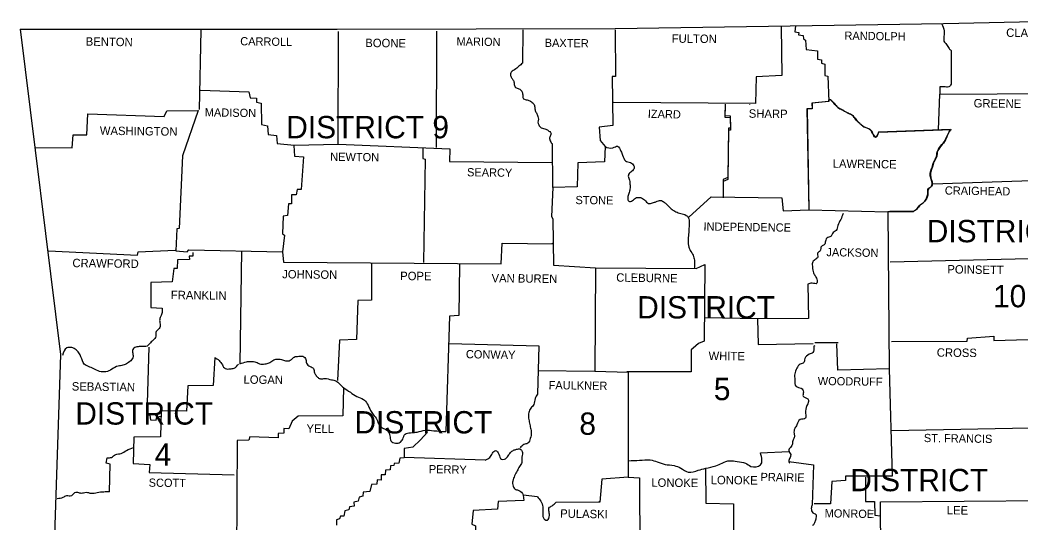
# Model space of a CAD drawing. Extents: x -42408 to 34530, y -43140 to 20491.
# Drawn here: x 1618 to 4174, y -21499 to -20216 of the extents above; entities that cross this region are included whole.
import ezdxf

# ---------------------------------------------------------------- set-up
doc = ezdxf.new("R2010")
doc.units = 0
for name, color, linetype in [('1', 7, 'Continuous'), ('2', 7, 'Continuous'), ('3', 7, 'Continuous'), ('S_MISC_BOUNDARY', 7, 'Continuous')]:
    doc.layers.add(name, color=color, linetype=linetype)

msp = doc.modelspace()

# ---------------------------------------------------------------- linework, layer by layer
at = {"layer": '1'}
for p, q in [((3966.6, -20386.8), (3966.6, -20405.3)), ((3688.2, -20420.3), (3682.6, -20420.5)), ((3994.6, -20496), (3810.4, -20502.4)), ((3963.1, -20497.5), (3964, -20496.6)), ((3802.9, -20516), (3807.7, -20511.2)), ((3647.7, -21040.7), (3707.3, -21040.7))]:
    msp.add_line(p, q, dxfattribs=at)
for points in [[(1618, -20239.1), (2427.6, -20239.6), (3138, -20238.1), (3976.1, -20225.1), (4364.6, -20216.1)], [(1618, -20239.1), (1721.6, -21071.2), (1676.6, -22429.5)], [(2080.1, -20242.1), (2075.6, -20444.9)], [(2079.1, -20395.3), (2202.3, -20399.3), (2205.3, -20415.3), (2222.3, -20415.8), (2221.8, -20425.8), (2233.8, -20428.8), (2234.8, -20483.4), (2250.3, -20486.9), (2251.3, -20508.5), (2273.3, -20511.5), (2274.3, -20531.5), (2317.9, -20536), (2430.1, -20533.5), (2431.1, -20245.6)], [(2681.9, -20244.6), (2680.4, -20542)], [(2902.2, -20241.1), (2901.2, -20326.7)], [(3138, -20241.1), (3139, -20360.3), (3130.5, -20360.8), (3132, -20485.4), (3096.9, -20490.4), (3099.9, -20524), (3112, -20539.5), (3111, -20579), (3042.9, -20581.6), (3040.4, -20642.6), (2978.3, -20644.6), (2975.3, -20718.7), (2978.8, -20724.7), (2980.3, -20842.9), (3087.4, -20849.9), (3085.9, -21113.8), (3171, -21116.3), (3171, -21384.6), (3104, -21389.6), (3098.9, -21448.7), (2986.3, -21449.2)], [(3562.1, -20233.6), (3563.1, -20357.8), (3498, -20361.3), (3496, -20429.3), (3134, -20427.3)], [(3598.5, -20230.9), (3596.6, -20246.1), (3606.6, -20247.6), (3606.1, -20253.6), (3617.6, -20256.1), (3618.6, -20264.1), (3624.1, -20267.6), (3625.7, -20291.7), (3654.2, -20294.7), (3654.2, -20316.2), (3664.7, -20317.7), (3664.7, -20326.2), (3673.7, -20328.7), (3673.2, -20357.8), (3681.2, -20359.3), (3683.2, -20424.8), (3640.7, -20428.8), (3641.2, -20442.9), (3628.2, -20443.4), (3632.7, -20701.7), (3834.4, -20706.2), (3837.9, -21107.8), (3706.3, -21111.3), (3703.8, -21043.7)], [(3995.6, -20293.7), (3996.1, -20380.3)], [(3682.6, -20420.5), (3682.7, -20424.8), (3640.2, -20428.8), (3640.7, -20442.9), (3627.7, -20443.4), (3632.2, -20701.7), (3833.9, -20706.2)], [(3964, -20497.1), (3966.6, -20405.3), (3966.6, -20405.3), (4259.5, -20403.8), (4263.5, -20442.9), (4346.1, -20439.9)], [(1657.5, -20542), (1751.2, -20542.5), (1753.7, -20509.5), (1788.2, -20509.5), (1791.2, -20455.9), (1986.5, -20462.9), (1992.5, -20447.9), (2073.1, -20447.4), (2032.5, -20563.5), (2024.5, -20749.3), (2018.5, -20749.8), (2015.5, -20805.9), (2045, -20808.4), (2049.5, -20803.8), (2288.4, -20808.4), (2290.9, -20834.9)], [(3418.9, -20430.9), (3417.9, -20459.9), (3431.9, -20460.9), (3432.4, -20492.9), (3427.4, -20492.9), (3425.4, -20619.1), (3413.9, -20624.1), (3413.9, -20666.2)], [(3418.9, -20435.4), (3417.9, -20464.4), (3431.9, -20465.4), (3432.4, -20497.4), (3427.4, -20497.4), (3425.4, -20623.6), (3413.9, -20628.6), (3413.9, -20670.7)], [(3481.5, -20431.9), (3482, -20431.4)], [(3810.9, -20502.4), (3996.6, -20495.9)], [(3994.6, -20496.4), (3994.6, -20496)], [(2316.9, -20537), (2318.9, -20564), (2341.9, -20565.5), (2335.9, -20649.6), (2325.4, -20649.1), (2323.4, -20662.7), (2311.4, -20662.7), (2310.9, -20685.7), (2303.4, -20686.2), (2300.9, -20715.7), (2289.9, -20717.2), (2288.4, -20762.3), (2293.4, -20765.8), (2288.4, -20808.4)], [(2430.1, -20533.5), (2715.4, -20545.5), (2714.9, -20578), (2976.8, -20580.1)], [(2646.8, -20544), (2646.3, -20570), (2652.9, -20571.5), (2648.8, -20835.9)], [(2978.3, -20644.6), (2977.8, -20532)], [(3949.1, -20634.6), (4227, -20625.6), (4243.5, -20606.6)], [(3325.8, -20719.7), (3382.8, -20668.2), (3563.1, -20670.7), (3566.6, -20704.2), (3632.2, -20701.7)], [(3833.9, -20706.2), (3838.4, -20705.2), (3899.5, -20705.2)], [(3900, -20705.2), (3838.9, -20705.2), (3834.4, -20706.2)], [(1690.6, -20806.4), (1918.4, -20816.9), (1919.4, -20808.9), (2014.5, -20804.3)], [(2183.2, -20806.4), (2179.7, -21095.2)], [(2290.9, -20834.9), (2846.6, -20839.4), (2849.1, -20786.8), (2978.3, -20788.3)], [(2976.8, -20787.8), (2978.3, -20786.3)], [(2059.6, -20810.4), (2059.6, -20819.4), (2050, -20819.4), (2050.5, -20828.4), (2020, -20828.9), (2019.5, -20851.4), (2011, -20851.4), (2006.5, -20885), (1952.4, -20887.5), (1951.9, -20951), (1981, -20953)], [(4301.1, -20824.4), (3839.9, -20834.9)], [(2515.7, -20838.9), (2515.2, -20932.5), (2480.6, -20933), (2477.6, -21032.7), (2433.6, -21034.2), (2428.6, -21137.3)], [(2740, -20841.4), (2739, -20971.6), (2714.9, -20973.6), (2705.4, -21268)], [(3087.4, -20849.9), (3344.8, -20851.4), (3366.8, -20840.9), (3365.3, -21036.7), (3350.3, -21043.2), (3336.8, -21054.7), (3332.3, -21059.2), (3331.8, -21115.3), (3168, -21115.3)], [(3630.2, -20891), (3631.2, -20979.1), (3501, -20979.6), (3367.3, -20977.1)], [(3501, -20979.6), (3503, -21045.2), (3643.7, -21042.7)], [(3843.9, -21037.7), (4037.2, -21036.7), (4037.7, -21029.7), (4104.8, -21024.6), (4104.8, -21035.2), (4396.2, -21027.1)], [(1946.9, -21052.2), (1941.9, -21224.4), (1949.4, -21226.4), (1950.9, -21238.4), (1965.9, -21239.4), (1967.4, -21230.9), (1979.5, -21228.9)], [(2713.9, -21043.2), (2942.7, -21048.7), (2939.7, -21172.3)], [(3647.7, -21049.2), (3645.2, -21049.7)], [(2115.1, -21079.2), (2111.6, -21150.8), (2046.5, -21151.3), (2043, -21216.4), (1978.5, -21214.9), (1976.5, -21282), (1908.9, -21282.5), (1906.9, -21349.6), (1949.4, -21352.1), (1947.9, -21372.6), (2165.2, -21378.6)], [(2940.2, -21111.8), (3085.9, -21113.8)], [(3837.9, -21107.8), (3845.4, -21382.1), (3726.3, -21382.6), (3725.8, -21393.6), (3691.2, -21395.6), (3688.2, -21452.7), (3646.2, -21452.7)], [(2444.1, -21155.8), (2442.1, -21227.9), (2327.9, -21228.4), (2312.9, -21241.4), (2304.4, -21261.5), (2291.9, -21260.5), (2291.4, -21272), (2276.9, -21273.5), (2277.4, -21284), (2204.8, -21282), (2202.3, -21290), (2172.2, -21291), (2171.2, -21583.9)], [(3843.9, -21265.5), (4241.5, -21257.5)], [(2658.9, -21270), (2640.8, -21289.5), (2621.3, -21308), (2598.8, -21311.5), (2598.8, -21335.1), (2587.8, -21336.6), (2585.8, -21348.6), (2573.2, -21349.6), (2572.2, -21355.1), (2563.7, -21355.6), (2563.2, -21366.1), (2551.2, -21366.6), (2550.2, -21378.6), (2540.2, -21378.6), (2540.7, -21392.6), (2529.7, -21391.6), (2529.2, -21402.6), (2515.7, -21403.6), (2511.7, -21421.7), (2494.6, -21423.2), (2493.1, -21433.2), (2484.1, -21435.7), (2481.6, -21446.2), (2470.1, -21448.7), (2471.1, -21459.2), (2459.6, -21460.2), (2457.6, -21468.2), (2447.1, -21471.2), (2444.6, -21484.8), (2436.6, -21484.3), (2434.1, -21491.3), (2426.6, -21493.8), (2426.1, -21507.3)], [(3509, -21322.5), (3581.6, -21319)], [(1846.3, -21422.2), (1847.8, -21351.6), (1837.8, -21348.6), (1840.8, -21335.1)], [(2805.6, -21341.1), (2599.3, -21334.6)], [(3368.8, -21361.6), (3369.8, -21451.2), (3440.4, -21452.7), (3440.9, -21645)], [(3581.6, -21345.1), (3644.2, -21353.1), (3640.7, -21455.2)], [(3171, -21384.6), (3200.1, -21386.6), (3200.6, -21577.9), (3174.5, -21686.5), (3230.1, -21689), (3229.6, -21781.2)], [(3777.4, -21385.1), (3776.9, -21447.2), (3799.9, -21447.2), (3800.9, -21481.8), (3815.4, -21483.3)], [(2939.2, -21434.7), (2903.2, -21430.7), (2904.7, -21444.2), (2839.1, -21446.7), (2837.1, -21466.2), (2775.5, -21469.7), (2772, -21504.8), (2781, -21509.3), (2781, -21532.3)], [(3096.4, -21448.2), (3098.9, -21445.7)], [(3843.9, -21891.3), (3883, -21888.8), (3882.5, -21787.2), (3845.9, -21784.7), (3847.9, -21585.9), (3816.4, -21581.4), (3815.4, -21447.7), (4242.5, -21444.7)]]:
    msp.add_lwpolyline(points, dxfattribs=at)
for points in [[(3971.3, -20225.1), (3978.1, -20244.1), (3977.6, -20257.6), (3977.6, -20270.1), (3984.1, -20278.6), (3990.6, -20289.2), (3995.6, -20293.7)], [(2901.2, -20326.7), (2892.2, -20334.2), (2884.2, -20341.2), (2872.1, -20349.7), (2870.6, -20357.8), (2874.6, -20365.8), (2878.7, -20372.3), (2880.2, -20381.3), (2883.7, -20388.8), (2892.2, -20391.8), (2899.2, -20398.3), (2901.7, -20407.3), (2902.7, -20415.8), (2910.7, -20419.8), (2919.7, -20422.8), (2928.2, -20428.8), (2932.2, -20436.4), (2933.2, -20445.9), (2936.7, -20453.4), (2940.7, -20462.4), (2941.7, -20469.9), (2940.7, -20477.4), (2942.7, -20484.4), (2949.2, -20491.4), (2960.8, -20494.9), (2968.8, -20499.9), (2974.3, -20507), (2970.8, -20515.5), (2971.3, -20523), (2975.8, -20532)], [(3996.1, -20380.3), (3989.6, -20386.8), (3977.1, -20386.8), (3966.6, -20386.8)], [(3810.4, -20502.4), (3802.4, -20516), (3794.9, -20505.5), (3789.4, -20496.9), (3772.8, -20488.9), (3762.3, -20480.4), (3751.8, -20469.9), (3744.3, -20460.4), (3732.8, -20454.4), (3719.8, -20446.9), (3708.8, -20441.4), (3699.2, -20431.9), (3688.2, -20420.3)], [(3688.7, -20420.3), (3699.8, -20431.9), (3709.3, -20441.4), (3720.3, -20446.9), (3733.3, -20454.4), (3744.8, -20460.4), (3752.3, -20469.9), (3762.8, -20480.4), (3773.3, -20488.9), (3789.9, -20496.9), (3795.4, -20505.5), (3802.9, -20516), (3810.9, -20502.4)], [(3899.5, -20705.2), (3907, -20700.2), (3917, -20688.7), (3926.6, -20681.2), (3933.1, -20671.2), (3936.1, -20661.2), (3938.1, -20646.6), (3945.6, -20641.1), (3946.6, -20629.6), (3943.1, -20617.1), (3943.1, -20604.6), (3947.6, -20592.6), (3951.6, -20578.5), (3958.6, -20564.5), (3960.1, -20554), (3969.1, -20538.5), (3981.1, -20522.5), (3987.1, -20508.5), (3994.6, -20496.4)], [(3995.1, -20496.4), (3987.6, -20508.5), (3981.6, -20522.5), (3969.6, -20538.5), (3960.6, -20554), (3959.1, -20564.5), (3952.1, -20578.5), (3948.1, -20592.6), (3943.6, -20604.6), (3943.6, -20617.1), (3947.1, -20629.6), (3946.1, -20641.1), (3938.6, -20646.6), (3936.6, -20661.2), (3933.6, -20671.2), (3927.1, -20681.2), (3917.5, -20688.7), (3907.5, -20700.2), (3900, -20705.2)], [(3112, -20539.5), (3132, -20543), (3144, -20538.5), (3152.5, -20551.5), (3157, -20561.5), (3164.5, -20576), (3176.6, -20580.6), (3185.6, -20588.6), (3185.6, -20597.1), (3177.6, -20605.1), (3171.5, -20613.1), (3173.5, -20622.6), (3175.6, -20635.6), (3175.6, -20648.1), (3172.5, -20659.7), (3170, -20670.2), (3172.5, -20679.2), (3182.1, -20677.7), (3192.1, -20670.2), (3202.6, -20670.2), (3212.6, -20675.7), (3223.1, -20685.2), (3233.6, -20683.2), (3242.1, -20680.7), (3254.2, -20677.2), (3262.7, -20681.7), (3270.2, -20687.7), (3279.2, -20697.2), (3287.7, -20703.2), (3298.7, -20708.7), (3312.2, -20712.2), (3324.7, -20720.7), (3326.8, -20735.3), (3326.3, -20747.8), (3325.3, -20763.3), (3324.2, -20780.3), (3325.8, -20796.8), (3331.3, -20807.9), (3338.3, -20820.9), (3340.3, -20832.9), (3339.8, -20851.9)], [(3719.8, -20710.7), (3713.8, -20726.2), (3706.8, -20741.3), (3702.3, -20754.3), (3692.7, -20761.8), (3689.7, -20768.8), (3681.2, -20771.8), (3674.7, -20781.8), (3671.7, -20790.8), (3664.7, -20794.8), (3661.2, -20805.9), (3654.7, -20811.9), (3655.2, -20821.9), (3647.7, -20828.9), (3641.7, -20836.9), (3641.7, -20847.9), (3644.2, -20862.4), (3649.2, -20870.9), (3653.7, -20882), (3653.2, -20889), (3640.7, -20889), (3630.2, -20891)], [(1981, -20953), (1981, -20963.6), (1977, -20974.6), (1974.4, -20984.1), (1976, -20996.6), (1971.4, -21006.6), (1964.9, -21014.6), (1964.9, -21024.6), (1957.4, -21035.2), (1949.4, -21043.2), (1942.4, -21049.7), (1929.9, -21050.7), (1919.4, -21051.2), (1908.9, -21054.7), (1904.9, -21062.2), (1906.9, -21073.7), (1902.9, -21084.7), (1892.3, -21093.2), (1880.8, -21098.7), (1868.8, -21100.7), (1852.3, -21108.8), (1837.3, -21115.3), (1821.2, -21114.3), (1806.2, -21107.8), (1792.7, -21101.7), (1782.2, -21095.7), (1773.7, -21077.2), (1768.2, -21067.2), (1758.7, -21057.2), (1747.1, -21053.2), (1737.6, -21054.2), (1726.1, -21073.7)], [(3645.2, -21049.7), (3642.7, -21066.2), (3633.2, -21070.7), (3622.1, -21081.7), (3619.6, -21091.7), (3610.6, -21095.7), (3602.1, -21106.3), (3596.6, -21120.8), (3596.6, -21135.8), (3600.1, -21152.8), (3612.6, -21157.3), (3618.6, -21167.3), (3617.6, -21177.8), (3629.7, -21184.9), (3631.7, -21190.9), (3629.7, -21197.4), (3624.1, -21215.9), (3624.6, -21228.4), (3623.6, -21233.9), (3610.1, -21237.4), (3602.1, -21250.9), (3596.6, -21260.5), (3594.6, -21273), (3596.1, -21282), (3592.1, -21289), (3590.6, -21299.5), (3585.6, -21308.5), (3581.1, -21317), (3586.1, -21327), (3584.6, -21334.1), (3581.6, -21345.1), (3584.1, -21348.6)], [(2115.1, -21079.2), (2126.2, -21086.2), (2134.7, -21097.7), (2142.2, -21107.3), (2154.7, -21107.8), (2164.7, -21105.8), (2176.2, -21095.7)], [(2179.7, -21095.2), (2196.2, -21089.7), (2208.3, -21088.7), (2220.3, -21090.7), (2232.8, -21095.7), (2246.3, -21094.7), (2256.3, -21091.2), (2266.3, -21084.7), (2277.4, -21082.7), (2287.9, -21084.7), (2298.9, -21087.7), (2310.9, -21084.2), (2317.9, -21077.7), (2329.9, -21075.7), (2340.4, -21075.7), (2347.9, -21084.2), (2349.4, -21093.2), (2359, -21101.7), (2367.5, -21107.3), (2370, -21117.8), (2374.5, -21125.3), (2379, -21130.3), (2385.5, -21133.3), (2396.5, -21132.3), (2413.5, -21135.8), (2424.5, -21138.3), (2434.6, -21146.8), (2444.1, -21155.8)], [(2444.1, -21155.8), (2461.6, -21167.8), (2478.1, -21178.3), (2495.1, -21185.9), (2504.7, -21196.9), (2513.2, -21213.9), (2520.2, -21224.4), (2529.2, -21237.4), (2535.7, -21251.9), (2546.2, -21260), (2557.2, -21267), (2562.7, -21279.5), (2565.2, -21292), (2577.3, -21298), (2588.8, -21295.5), (2595.3, -21288), (2601.3, -21275), (2614.8, -21271), (2632.3, -21269.5), (2652.4, -21265), (2674.4, -21266), (2705.4, -21268)], [(2939.7, -21172.3), (2933.2, -21183.9), (2930.2, -21198.9), (2922.2, -21208.4), (2917.2, -21219.4), (2916.7, -21233.9), (2919.2, -21246.9), (2921.7, -21259.5), (2923.7, -21271), (2921.2, -21285.5), (2914.7, -21298), (2904.7, -21301.5), (2895.2, -21310)], [(1840.8, -21335.1), (1851.8, -21334.1), (1862.3, -21327), (1876.3, -21324), (1890.3, -21316.5), (1907.9, -21308.5)], [(2805.6, -21341.1), (2818.1, -21334.1), (2824.6, -21323.5), (2832.6, -21317), (2840.6, -21326), (2847.6, -21339.1), (2855.1, -21339.1), (2864.6, -21330.1), (2870.6, -21322), (2878.2, -21316), (2886.2, -21313.5), (2894.7, -21312.5), (2901.2, -21322), (2899.2, -21337.1), (2899.2, -21347.1), (2893.7, -21357.6), (2887.7, -21368.6), (2881.2, -21381.1), (2876.2, -21394.6), (2877.2, -21407.7), (2884.2, -21416.2), (2892.2, -21418.7), (2903.2, -21429.7)], [(3172, -21342.6), (3200.1, -21341.6), (3227.6, -21340.6), (3245.1, -21345.6), (3265.2, -21352.1), (3288.7, -21355.1), (3305.2, -21361.6), (3324.7, -21371.6), (3349.8, -21367.1), (3369.3, -21362.1), (3394.8, -21355.6), (3411.4, -21348.6), (3430.4, -21342.6), (3449.4, -21345.1), (3470.9, -21349.1), (3484.5, -21357.1), (3509, -21353.6), (3509, -21322.5)], [(1846.3, -21422.2), (1831.8, -21422.7), (1815.2, -21424.7), (1800.2, -21426.7), (1786.7, -21424.2), (1774.2, -21426.2), (1765.7, -21424.2), (1755.2, -21426.7), (1749.1, -21432.7), (1736.6, -21432.7), (1727.6, -21436.7), (1713.1, -21440.2)], [(2939.2, -21434.7), (2947.7, -21445.7), (2952.8, -21460.7), (2952.8, -21477.7), (2956.8, -21491.8), (2964.8, -21494.8), (2969.8, -21482.8), (2968.8, -21470.7), (2968.8, -21463.7), (2977.3, -21457.7), (2986.3, -21449.2)], [(3640.7, -21455.2), (3638.7, -21465.2), (3642.7, -21475.7), (3649.7, -21479.3), (3650.7, -21489.3), (3648.2, -21499.3), (3646.2, -21503.3), (3641.7, -21509.3)]]:
    msp.add_spline(points, degree=3, dxfattribs=at)
at = {"layer": 'S_MISC_BOUNDARY'}
msp.add_line((3688.7, -20420.3), (3683.1, -20420.5), dxfattribs=at)

# ---------------------------------------------------------------- texts
at = {"layer": '2'}
for s, height, rotation, p in [('CLAY', 21.52, 359.2258, (4136.3, -20259.1)), ('BENTON', 21.53, 359.2527, (1785.7, -20281.7)), ('CARROLL', 21.03, 359.1481, (2180.2, -20280.7)), ('BOONE', 21.53, 359.4001, (2499.6, -20285.2)), ('MARION', 21.03, 359.1854, (2732.5, -20281.2)), ('BAXTER', 21.03, 359.2559, (2957.8, -20284.7)), ('FULTON', 21.52, 359.4996, (3282.2, -20274.1)), ('RANDOLPH', 21.03, 359.2583, (3723.3, -20266.6)), ('GREENE', 21.53, 359.2361, (4053.2, -20439.4)), ('MADISON', 21.03, 359.0906, (2089.6, -20462.4)), ('IZARD', 21.02, 358.9258, (3221.1, -20466.4)), ('SHARP', 21.52, 359.3905, (3479, -20465.9)), ('WASHINGTON', 21.52, 359.232, (1821.7, -20509.5)), ('NEWTON', 21.03, 359.2717, (2410, -20576)), ('LAWRENCE', 21.53, 359.2678, (3693.3, -20593.7)), ('SEARCY', 21.02, 359.2527, (2759.5, -20615.6)), ('CRAIGHEAD', 21.03, 359.1159, (3979.6, -20662.2)), ('STONE', 21.02, 359.4001, (3036.4, -20686.7)), ('INDEPENDENCE', 21.022, 359.2187, (3363.3, -20754.3)), ('JACKSON', 21.02, 359.1352, (3677.2, -20819.9)), ('CRAWFORD', 21.52, 359.2771, (1751.7, -20847.9)), ('JOHNSON', 21.53, 359.3514, (2287.4, -20876.4)), ('POINSETT', 21.52, 359.1987, (3986.1, -20863.9)), ('POPE', 21.53, 359.6155, (2588.8, -20881)), ('VAN BUREN', 21.53, 359.3508, (2822.1, -20886.5)), ('CLEBURNE', 21.52, 359.2535, (3140.5, -20885)), ('FRANKLIN', 21.53, 359.1815, (2003, -20929.5)), ('CONWAY', 21.02, 359.0371, (2756.5, -21080.7)), ('CROSS', 21.52, 359.3839, (3959.1, -21076.7)), ('WHITE', 21.53, 359.3139, (3376.3, -21085.2)), ('LOGAN', 21.53, 359.3969, (2188.7, -21145.8)), ('FAULKNER', 21.03, 359.2486, (2967.8, -21159.8)), ('WOODRUFF', 21.02, 359.2748, (3655.2, -21149.3)), ('SEBASTIAN', 21.52, 359.2816, (1750.1, -21163.3)), ('YELL', 21.53, 359.1987, (2349.4, -21271)), ('ST. FRANCIS', 21.022, 359.2216, (3926.1, -21295)), ('PERRY', 21.03, 359.0858, (2661.9, -21374.6)), ('SCOTT', 21.03, 359.4063, (1946.4, -21409.2)), ('LONOKE', 21.53, 359.4974, (3230.1, -21409.2)), ('LONOKE', 21.53, 359.4974, (3381.8, -21402.6)), ('PRAIRIE', 21.03, 359.2116, (3509, -21394.6)), ('PULASKI', 21.53, 359.053, (2997.3, -21488.3)), ('MONROE', 21.02, 359.0331, (3672.7, -21487.3)), ('LEE', 21.53, 359.4327, (3984.6, -21479.8))]:
    msp.add_text(s, height=height, rotation=rotation, dxfattribs=at).set_placement(p)
at = {"layer": '3'}
for s, height, p in [('DISTRICT 9', 57.08, (2297.9, -20518.5)), ('DISTRICT', 57.08, (3933.6, -20784.3)), ('10', 57.08, (4102.8, -20950.5)), ('DISTRICT', 57.08, (3194.1, -20979.1)), ('5', 57.1, (3389.8, -21187.9)), ('DISTRICT', 57.08, (1759.2, -21250.4)), ('DISTRICT', 57.08, (2472.1, -21273)), ('8', 57.1, (3046.4, -21276.5)), ('4', 57.1, (1961.9, -21355.6)), ('DISTRICT', 57.08, (3738.3, -21420.7))]:
    msp.add_text(s, height=height, dxfattribs=at).set_placement(p)

doc.saveas('drawing.dxf')
